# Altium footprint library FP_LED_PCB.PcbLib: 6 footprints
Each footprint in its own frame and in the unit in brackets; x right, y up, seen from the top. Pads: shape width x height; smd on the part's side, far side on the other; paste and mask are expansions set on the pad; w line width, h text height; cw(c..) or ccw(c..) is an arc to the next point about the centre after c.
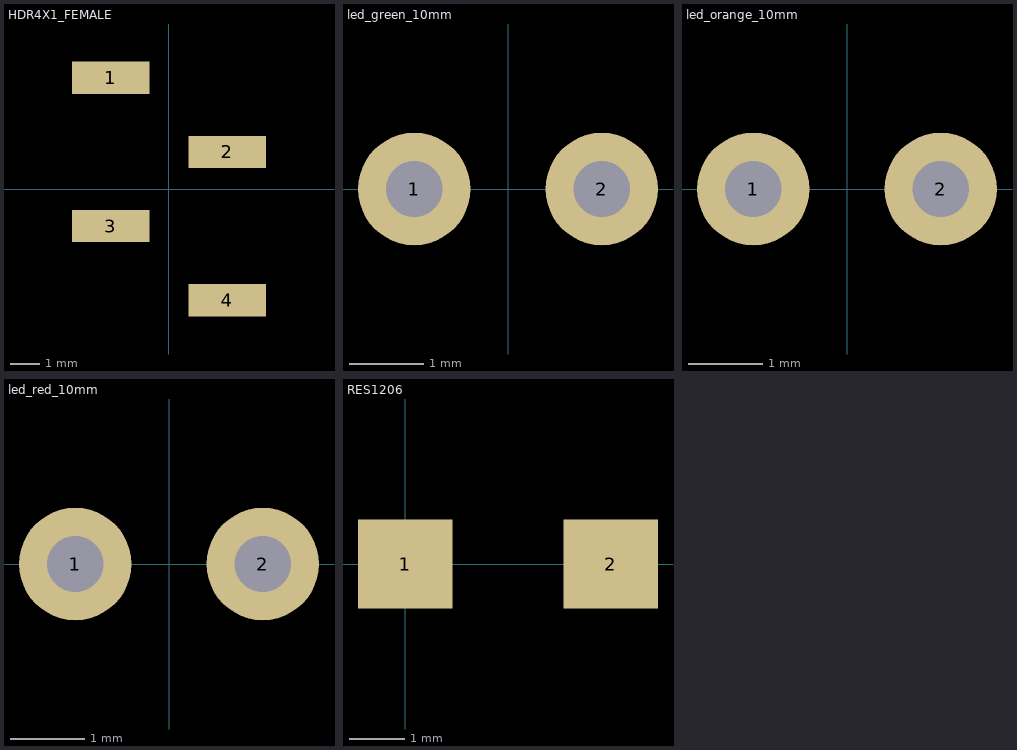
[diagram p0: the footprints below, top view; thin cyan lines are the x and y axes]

## HDR4X1_FEMALE [mm]
pads (4):
  rect 2.65x1.1 smd: 1(-2,3.81) 2(2,1.27) 3(-2,-1.27) 4(2,-3.81)
3D body "2MM-SMD-PIN-HEADER-FEMALE.STEP": height 2.33, standoff 0.01, extent -2.762,-3.893 2.738,4.147

## led_green_10mm [mil]
pads (2):
  round 60 hole 30: 1(-50,0) 2(50,0)
3D body "LED 10mm Green.step": height 551.68, standoff -221.94, extent -216.54,-216.41 216.05,216.41

## led_orange_10mm [mil]
pads (2):
  round 60 hole 30: 1(-50,0) 2(50,0)
3D body "LED 10mm Orange.step": height 551.68, standoff -221.94, extent -216.54,-216.41 216.05,216.41

## led_red_10mm [mil]
pads (2):
  round 60 hole 30: 1(-50,0) 2(50,0)
3D body "LED 10mm Red.step": height 551.68, standoff -221.94, extent -216.54,-216.41 216.05,216.41

## PCBComponent_1 [mil]

## RES1206 [mm]
pads (2):
  rect 1.7x1.6 smd: 1(0,0) 2(3.7,0)
3D body "RC1206.stp": height 0.55, standoff 0, extent 0.253,-0.787 3.353,0.813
